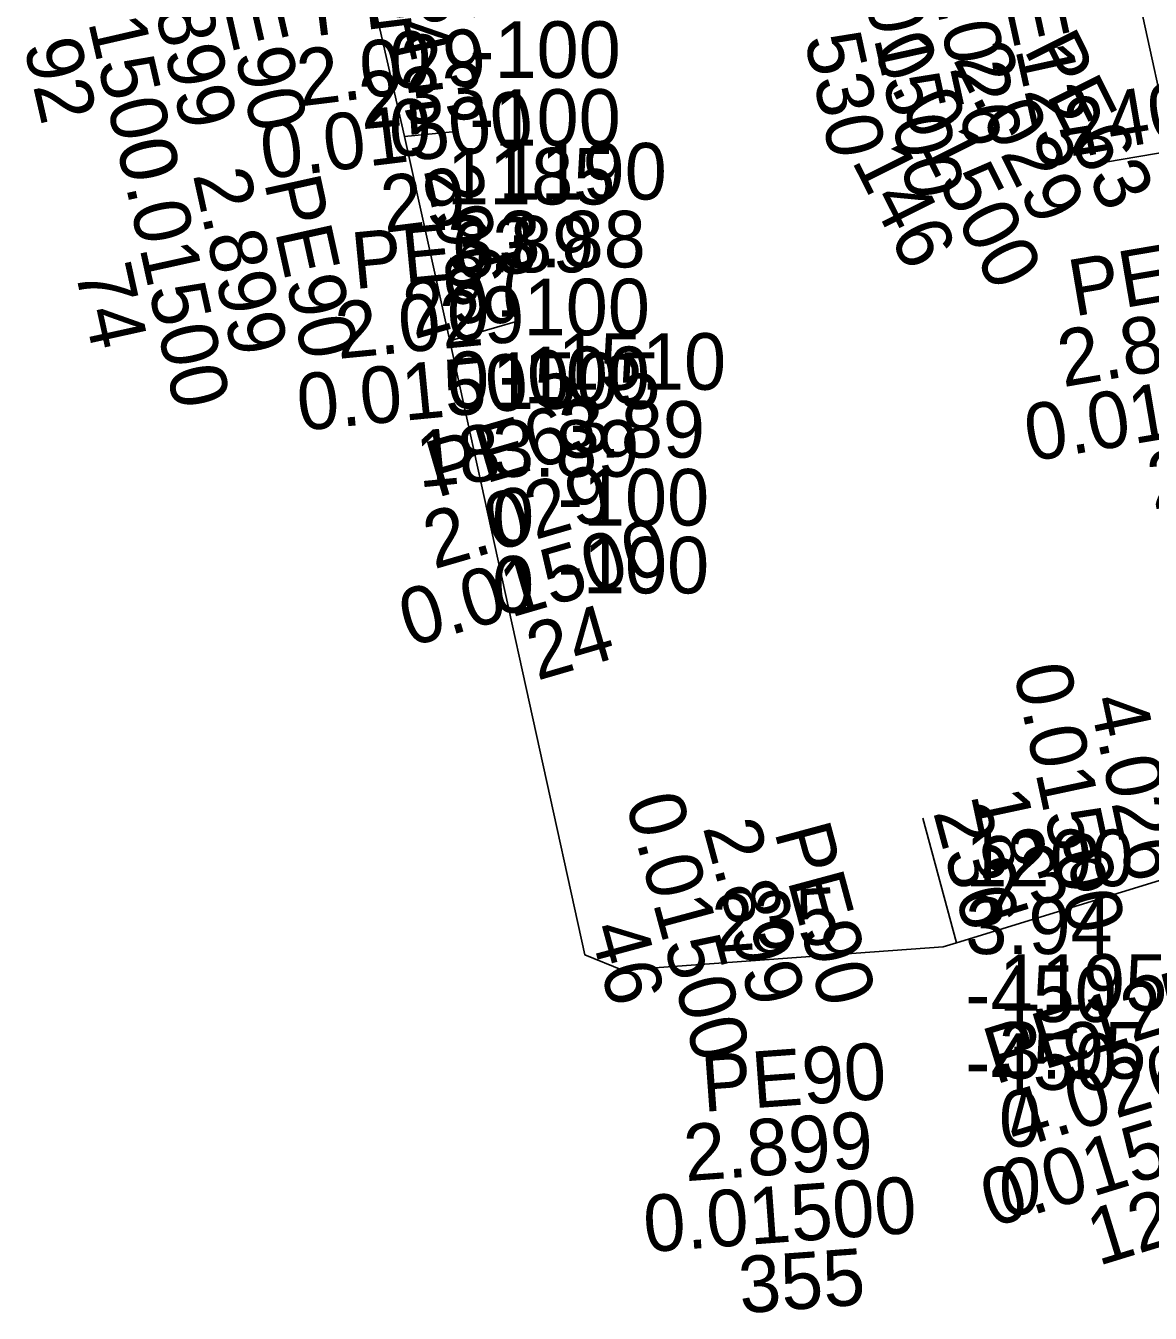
# Model space of a CAD drawing. Extents: x 607463 to 609569, y 4065893 to 4067650.
# Drawn here: x 607571.2 to 607968.7, y 4066283.8 to 4066738.9 of the extents above; entities that cross this region are included whole.
import ezdxf

# ---------------------------------------------------------------- set-up
doc = ezdxf.new("R2010")
doc.units = 0
for name, color, linetype in [('GW_NATT', 7, 'Continuous'), ('GW_NODETX', 7, 'Continuous'), ('GW_PATT', 7, 'Continuous'), ('PE125', 7, 'Continuous'), ('PE63', 7, 'Continuous'), ('PE90', 7, 'Continuous')]:
    doc.layers.add(name, color=color, linetype=linetype)

msp = doc.modelspace()

# ---------------------------------------------------------------- linework, layer by layer
at = {"layer": 'PE125'}
msp.add_lwpolyline([(608012.31, 4066466.75), (607973.5, 4066437.25), (607900.19, 4066414.75)], dxfattribs=at)
at = {"layer": 'PE63'}
for p, q in [((607705.12, 4066699.75), (607723.31, 4066701.5)), ((607721.06, 4066627.5), (607744.25, 4066634.25))]:
    msp.add_line(p, q, dxfattribs=at)
at = {"layer": 'PE90'}
for p, q in [((607976.38, 4066694.75), (607930.19, 4066906)), ((607705.12, 4066699.75), (607684.62, 4066789)), ((607721.06, 4066627.5), (607705.12, 4066699.75)), ((607976.38, 4066694.75), (607952.81, 4066690.75)), ((607900.19, 4066414.75), (607888.31, 4066458.75))]:
    msp.add_line(p, q, dxfattribs=at)
msp.add_lwpolyline([(607900.19, 4066414.75), (607895.5, 4066413.25), (607782.19, 4066405), (607768.81, 4066410.5), (607721.06, 4066627.5)], dxfattribs=at)

# ---------------------------------------------------------------- texts
at = {"layer": 'GW_NATT'}
for s, p in [('-100 ', (607728, 4066720.5)), ('0 ', (607699.62, 4066717)), ('-100 ', (607728, 4066696.5)), ('0 ', (607699.62, 4066693)), ('3.89 ', (607720.12, 4066651.75)), ('3.88 ', (607738.31, 4066653.5)), ('0 ', (607720.12, 4066627.75)), ('-100 ', (607738.31, 4066629.5)), ('0 ', (607720.12, 4066603.75)), ('-100 ', (607738.31, 4066605.5)), ('3.89 ', (607759.25, 4066586.25)), ('3.89 ', (607736.04, 4066579.48)), ('-100 ', (607759.25, 4066562.25)), ('0 ', (607736.04, 4066555.48)), ('-100 ', (607759.25, 4066538.25)), ('0 ', (607736.04, 4066531.48)), ('3.94 ', (607903.31, 4066410.75)), ('-450 ', (607903.31, 4066386.75)), ('-450 ', (607903.31, 4066362.75)), ('3.95 ', (607915.2, 4066366.7)), ('0 ', (607915.2, 4066342.7)), ('0 ', (607915.2, 4066318.7))]:
    msp.add_text(s, height=20, dxfattribs=at).set_placement(p)
at = {"layer": 'GW_NODETX'}
for s, p in [('1190', (607738.31, 4066677.5)), ('1185', (607720.12, 4066675.75)), ('1510', (607759.25, 4066610.25)), ('1505', (607736.04, 4066603.48)), ('1200', (607903.31, 4066434.75)), ('1195', (607915.2, 4066390.7))]:
    msp.add_text(s, height=20, dxfattribs=at).set_placement(p)
at = {"layer": 'GW_PATT'}
for s, rotation, p in [('0.01500', 282.94, (607584.88, 4066776.57)), ('234', 282.94, (607693.4, 4066768.66)), ('0.01500', 282.39, (607862.94, 4066770.87)), ('2.899', 282.94, (607611.85, 4066766.35)), ('PE90', 282.94, (607637.03, 4066763.92)), ('PE125', 282.39, (607913.25, 4066765.54)), ('PE63', 7.03, (607673.42, 4066735.22)), ('4.026', 282.39, (607889.81, 4066760.39)), ('2.029', 7.03, (607668.42, 4066710.42)), ('92', 282.94, (607570.44, 4066732.21)), ('530', 282.39, (607846.36, 4066734.46)), ('0.01500', 296.57, (607870.14, 4066730.62)), ('2.029', 296.57, (607898.76, 4066727.04)), ('PE63', 296.57, (607923.8, 4066730.62)), ('233', 5.5, (607689.95, 4066702.31)), ('0.01500', 7.03, (607655.48, 4066684.65)), ('240', 9.63, (607940.26, 4066692.68)), ('0.01500', 282.44, (607603.38, 4066696.77)), ('146', 296.57, (607862.98, 4066691.26)), ('2.899', 282.44, (607630.26, 4066686.31)), ('29', 7.03, (607698.11, 4066665.72)), ('296', 282.44, (607711.83, 4066687.92)), ('PE90', 282.44, (607655.42, 4066683.67)), ('PE63', 5.5, (607687.35, 4066645.8)), ('PE90', 9.63, (607941.75, 4066636.13)), ('297', 16.23, (607708.49, 4066628.01)), ('74', 282.44, (607588.56, 4066652.54)), ('2.029', 5.5, (607681.68, 4066621.14)), ('2.899', 9.63, (607937.88, 4066611.13)), ('0.01500', 5.5, (607668.05, 4066595.72)), ('0.01500', 9.63, (607926.12, 4066584.79)), ('PE63', 16.23, (607716.47, 4066572)), ('18', 5.5, (607710.17, 4066575.66)), ('24', 9.63, (607969.57, 4066567.82)), ('2.029', 16.23, (607715.49, 4066546.72)), ('0.01500', 16.23, (607706.84, 4066519.21)), ('24', 16.23, (607751.95, 4066507.35)), ('0.01500', 282.09, (607920.24, 4066511.3)), ('4.026', 282.09, (607947.06, 4066500.69)), ('0.01500', 285.1, (607783.11, 4066464.76)), ('18', 282.09, (607905.15, 4066467.16)), ('236', 285.1, (607891.86, 4066460.96)), ('2.899', 285.1, (607810.45, 4066455.57)), ('PE90', 285.1, (607835.71, 4066454.1)), ('238', 17.06, (607912.73, 4066422.78)), ('235', 4.16, (607814.62, 4066411.37)), ('46', 285.1, (607770.36, 4066419.89)), ('PE125', 17.06, (607913.86, 4066364.55)), ('PE90', 4.16, (607810.7, 4066354.94)), ('4.026', 17.06, (607920.9, 4066341.61)), ('0.01500', 17.06, (607912.65, 4066313.97)), ('2.899', 4.16, (607804.47, 4066330.42)), ('0.01500', 4.16, (607790.25, 4066305.32)), ('125', 17.06, (607950.28, 4066300.42)), ('355', 4.16, (607823.91, 4066283.71))]:
    msp.add_text(s, height=20, rotation=rotation, dxfattribs=at).set_placement(p)

doc.saveas('drawing.dxf')
